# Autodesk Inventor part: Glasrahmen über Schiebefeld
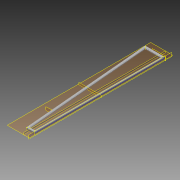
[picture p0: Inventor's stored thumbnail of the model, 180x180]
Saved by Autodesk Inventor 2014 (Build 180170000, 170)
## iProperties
Created: 2013-09
Part Number: Glasrahmen über Schiebefeld
Material: Stahl
Document SubType Name: Modeling
Designer: Stefan Tammegger
Mass: 6653.64 g
Surface Area: 7305.57 cm^2
Volume: 847.597 cm^3
Density: 7.85 g/cm^3
Appearance: Stahl
Author: Stefan Tammegger
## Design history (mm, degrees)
node "Blöcke"
  sketch "FSR 4020L"
    geometry: L1 (150.024, 72.958)-(150.024, 88.958); L2 (152.024, 90.958)-(152.024, 90.958); L3 (152.024, 68.958)-(116.024, 68.958); L4 (116.024, 68.958)-(116.024, 52.958); L5 (116.024, 52.958)-(152.024, 52.958); L6 (152.024, 52.958)-(152.024, 68.958); L7 (154.024, 88.958)-(154.024, 52.958); L8 (152.024, 50.958)-(116.024, 50.958); L9 (114.024, 52.958)-(114.024, 68.958); L10 (116.024, 70.958)-(148.024, 70.958); A1 r 2 centre (152.024, 88.958) between (152.024, 90.958) and (150.024, 88.958); A2 r 2 centre (152.024, 88.958) between (154.024, 88.958) and (152.024, 90.958); A3 r 2 centre (152.024, 52.958) between (152.024, 50.958) and (154.024, 52.958); A4 r 2 centre (148.024, 72.958) between (148.024, 70.958) and (150.024, 72.958); A5 r 2 centre (116.024, 68.958) between (116.024, 70.958) and (114.024, 68.958); A6 r 2 centre (116.024, 52.958) between (114.024, 52.958) and (116.024, 50.958); 7 further points
    constraints: 20 end point, 12 point on circle, 12 point on line, 12 tangent, 6 centre point, 5 equal radius, 4 perpendicular, 3 parallel, 1 midpoint, 1 other
    dimensions: "d0" = 40 distance of point (154.024, 90.958) point (154.024, 50.958); "d3" = 40 distance of point (154.024, 50.958) point (114.024, 50.958); "d4" = 20 distance of point (114.024, 50.958) point (114.024, 70.958); "d5" = 36 distance of point (114.024, 70.958) point (150.024, 70.958); "d6" = 20 distance of point (150.024, 70.958) point (150.024, 90.958); "d7" = 2 distance between parallel lines of L10 L3; "d8" = 2 radius of A1
  sketch "Glashalteleiste"
    geometry: L1 (1701.795, 161.278)-(1698.916, 161.278); L2 (1696.295, 159.278)-(1688.295, 159.278); L3 (1697.856, 160.838)-(1696.295, 159.278); L4 (1698.295, 161.278)-(1702.374, 161.278); L5 (1684.795, 161.278)-(1685.674, 161.278); L6 (1686.734, 160.838)-(1688.295, 159.278); L7 (1699.73, 145.667)-(1701.795, 146.274); L8 (1701.795, 146.274)-(1701.795, 142.778); L9 (1701.795, 142.778)-(1684.795, 142.778); L10 (1684.795, 142.778)-(1684.795, 159.778); L11 (1684.795, 159.778)-(1685.674, 159.778); L12 (1685.674, 159.778)-(1687.674, 157.778); L13 (1687.674, 157.778)-(1696.85, 157.778); L14 (1696.85, 157.778)-(1698.85, 159.778); L15 (1701.795, 157.278)-(1701.795, 159.778); L16 (1701.795, 159.778)-(1698.85, 159.778); L17 (1699.73, 145.667)-(1699.307, 147.106); L18 (1701.795, 157.278)-(1703.295, 157.278); L19 (1684.795, 141.278)-(1701.795, 141.278); L20 (1683.295, 159.778)-(1683.295, 142.778); L21 (1703.295, 142.778)-(1703.295, 146.274); L22 (1701.372, 147.713)-(1699.307, 147.106); L23 (1703.295, 159.778)-(1703.295, 157.278); A1 r 1.5 centre (1685.674, 159.778) between (1686.734, 160.838) and (1685.674, 161.278); A2 r 1.5 centre (1698.916, 159.778) between (1698.916, 161.278) and (1697.856, 160.838); A3 r 1.5 centre (1684.795, 142.778) between (1683.295, 142.778) and (1684.795, 141.278); A4 r 1.5 centre (1684.795, 159.778) between (1684.795, 161.278) and (1683.295, 159.778); A5 r 1.5 centre (1701.795, 142.778) between (1701.795, 141.278) and (1703.295, 142.778); A6 r 1.5 centre (1701.795, 159.778) between (1703.295, 159.778) and (1701.795, 161.278); A7 r 1.5 centre (1701.795, 146.274) between (1703.295, 146.274) and (1701.372, 147.713); 7 further points
    constraints: 46 end point, 14 point on circle, 14 point on line, 14 tangent, 7 centre point, 6 equal radius, 5 perpendicular, 3 parallel, 2 collinear, 2 horizontal, 1 midpoint, 6 other
    dimensions: "d43" = 20 distance of point (1683.295, 161.278) point (1703.295, 161.278); "d44" = 20 distance of point (1703.295, 161.278) point (1703.295, 141.278); "d45" = 7 distance of point (1703.295, 141.278) point (1703.295, 148.278); "d46" = 4 distance of point (1703.295, 161.278) L18.end; "d47" = 5 distance of point (1703.295, 161.278) L4.start; "d48" = 2 distance between parallel lines of L1 L2; "d49" = 135 deg angle of L3 L4; "d50" = 3 distance of point (1683.295, 161.278) point (1686.295, 161.278); "d51" = 1.5 distance between parallel lines of L20 L10; "d52" = 1.5 distance between parallel lines of L23 L15; "d53" = 1.5 distance between parallel lines of L22 L7 (derived); "d54" = 9.17588 distance of L12.end L13.end; "d55" = 20 distance of point (1683.295, 161.278) point (1683.295, 141.278); "d56" = 20 distance of point (1683.295, 141.278) point (1703.295, 141.278); "d57" = 4.157 distance of point (1703.295, 148.278) L17.end; "d58" = 1.5 radius of A3
workplane "Arbeitsebene1"
sketch "Skizze1"
  geometry: L1 (77, -3)-(77, -77) reference; L2 (-3, -77)-(-3, -3) reference; L3 (74, 0)-(0, 0) reference
  constraints: 2 horizontal
  dimensions: "d9" = 20 dimension on L2
  node "Referenz1"
  node "Referenz2"
  node "Referenz3"
  node "FSR 4020L:1" dims "d9" = 20
workplane "Arbeitsebene2"
extrude "Extrusion1" new body sketch "Skizze1" stored distance "d10" = 10; taper "d11" = 0 deg
workplane "Arbeitsebene3"
sketch "Skizze2"
  geometry: L1 (17, 2820)-(17, 0) reference; L2 (57, 2820)-(57, 0) reference; L3 (69, 2820)-(-4457.608, 2820) reference; 1 further point
  constraints: 1 horizontal, 1 vertical
extrude "Extrusion2" new body sketch "Skizze2" distance "d12" = 1000; taper "d13" = 0 deg
sketch "Skizze3"
  geometry: L1 (17, 2820)-(17, 0) reference; L2 (57, 2820)-(57, 0) reference; L3 (69, 0)-(-3759.656, 0) reference; 1 further point
  constraints: 1 vertical
extrude "Extrusion3" new body sketch "Skizze3" distance "d14" = 500; taper "d15" = 0 deg
workplane "Arbeitsebene4"
sketch "Skizze4"
  geometry: L1 (50, -26)-(50, 26) reference; L2 (478.406, 18)-(-517.789, 18) reference; 1 further point
  constraints: 1 horizontal, 1 vertical
extrude "Extrusion4" new body sketch "Skizze4" stored distance "d16" = 6000; taper "d17" = 0 deg
workplane "Arbeitsebene5"
feature "Trennen1"
feature "Trennen2"
workplane "Arbeitsebene6"
feature "Trennen3"
feature "Trennen4"
workplane "Arbeitsebene7"
feature "Trennen5"
feature "Trennen6"
workplane "Arbeitsebene9"
feature "Trennen7"
feature "Trennen8"
sketch "Skizze5"
  geometry: L1 (-32, 0)-(0, 0) reference; L2 (0, 2780)-(-32, 2780) reference; L3 (-32, 2780)-(-32, 0) reference; 4 further points
  dimensions: "d18" = 200 distance from line of L1 point (-16, 200); "d19" = 200 distance from line of point (-16, 2580) L2; "d20" = 2380 distance of point (-16, 200) point (-16, 2580); "d21" = 1190 distance of point (-16, 2580) point (-16, 1390); "d22" = 16 distance from line of L3 point (-16, 2580); "d23" = 16 distance from line of L3 point (-16, 1390); "d24" = 16 distance from line of L3 point (-16, 200) (derived)
hole "Bohrung1" sketch "Skizze5" at (-16, 200), (-16, 2580), (-16, 1390) diameter "d25" = 8; stored, may be unused: countersink angle "d29" = 90 deg, drill point angle "d31" = 118 deg; dims "d26" = 6, "d27" = 16, "d28" = 2, "d30" = 8
sketch "Skizze6"
  geometry: L1 (0, 2790.619)-(0, 0) reference; L2 (0, 2790.619)-(-32, 2790.619) reference; 3 further points
  dimensions: "d32" = 200 distance from line of point (-16, 2590.619) L2; "d33" = 16 distance from line of L1 point (-16, 2590.619); "d34" = 1500 distance of point (-16, 1090.619) point (-16, 2590.619); "d35" = 16 distance from line of L1 point (-16, 1090.619)
hole "Bohrung2" sketch "Skizze6" at (-16, 2590.619), (-16, 1090.619) diameter "d36" = 8; stored, may be unused: countersink angle "d40" = 90 deg, drill point angle "d42" = 118 deg; dims "d37" = 6, "d38" = 16, "d39" = 2, "d41" = 8
workplane "Arbeitsebene10"
sketch "Skizze7"
  geometry: L1 (389.541, 34)-(373.541, 34) reference; L2 (391.541, 0)-(391.541, 32) reference; 1 further point
  constraints: 1 vertical
  dimensions: "d59" = 9 dimension on L1
extrude "Extrusion5" new body sketch "Skizze7" stored distance "d60" = 6000; taper "d61" = 0 deg
workplane "Arbeitsebene11"
sketch "Skizze8"
  geometry: L1 (-32, 2780)-(0, 2780) reference; L2 (2, 2778)-(2, 2762) reference; L3 (-27, 0)-(-27, 2780) reference; 1 further point
  constraints: 1 horizontal, 1 vertical
  node "Glashalteleiste:3" dims "d0" = 40, "d3" = 40, "d4" = 20, "d5" = 36, "d6" = 20, "d7" = 2, "d8" = 2
sketch "Skizze9"
  geometry: L1 (-8.5, 0)-(-25.5, 0) reference; L2 (-27, 0)-(-27, 2780) reference; 1 further point
  constraints: 1 horizontal, 1 vertical
  node "Glashalteleiste:4"
workplane "Arbeitsebene12"
sketch "Skizze10"
  geometry: L1 (109.329, -31)-(351.621, -31) reference; L2 (-20, -36)-(-20, -4) reference; 1 further point
  constraints: 1 horizontal, 1 vertical
extrude "Extrusion6" new body sketch "Skizze10" stored distance "d64" = 6000; taper "d65" = 0 deg
extrude "Extrusion7" new body sketch "Skizze8" stored distance "d66" = 6000; taper "d67" = 0 deg
extrude "Extrusion8" new body sketch "Skizze9" stored distance "d68" = 6000; taper "d69" = 0 deg
workplane "Arbeitsebene13"
node "Volumenkörper1"
node "Referenz4"
node "Volumenkörper2"
node "Referenz5"
node "Volumenkörper3"
node "Referenz6"
node "Volumenkörper4"
node "Volumenkörper5"
node "Volumenkörper6"
node "Volumenkörper7"
node "Volumenkörper8"
node "FSR 4020L:3"
node "FSR 4020L:4"
node "FSR 4020L:6"
node "Glashalteleiste:1" dims "d59" = 9
node "Glashalteleiste:6"
feature "怀䁱"
